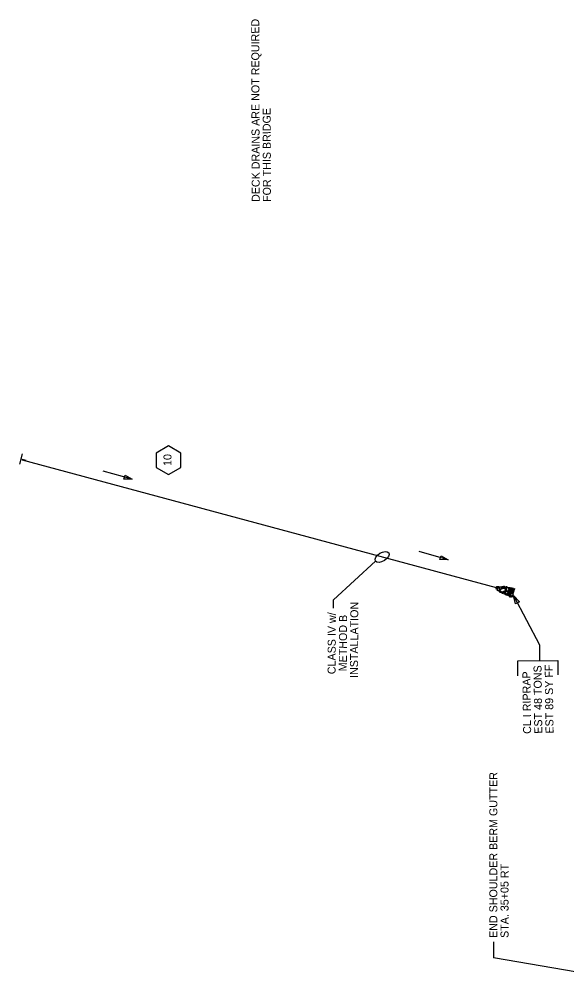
# Model space of a CAD drawing. Extents: x 2384780 to 2405432, y 547869 to 573706.
# Drawn here: x 2395017 to 2395359, y 553697 to 554302 of the extents above; entities that cross this region are included whole.
import ezdxf

# ---------------------------------------------------------------- set-up
doc = ezdxf.new("R2010")
doc.units = 0
for name, color, linetype in [('Old_Level_1', 7, 'Continuous'), ('Old_Level_10', 7, 'Continuous'), ('Old_Level_23', 7, 'Continuous'), ('Old_Level_5', 7, 'Continuous'), ('Prop Drainage Box Number Symbol CELL', 7, 'Continuous')]:
    doc.layers.add(name, color=color, linetype=linetype)

# ---------------------------------------------------------------- blocks, each defined once
blk = doc.blocks.new('RIPRAP')
at = {"layer": 'Old_Level_1'}
for points in [[(-0.002, -0.00625), (-0.00625, -0.00775), (-0.016, -0.0125), (-0.02, -0.00675), (-0.02, -0.003), (-0.008, 0.00275), (-0.002, -0.00025), (-0.002, -0.00625)], [(0.01825, -0.00325), (0.01375, -0.005), (0.00325, -0.00975), (0.00025, -0.00375), (0, 0), (0.01125, 0.005), (0.018, 0.00275), (0.01825, -0.00325)], [(-0.046, -0.12775), (-0.0505, -0.12425), (-0.053, -0.1145), (-0.0485, -0.11), (-0.04475, -0.11), (-0.04, -0.12175), (-0.04225, -0.12625), (-0.046, -0.12775)], [(-0.0485, -0.08525), (-0.0425, -0.0835), (-0.03275, -0.0825), (-0.0305, -0.08925), (-0.03175, -0.0945), (-0.0445, -0.09325), (-0.049, -0.089), (-0.0485, -0.08525)], [(-0.046, -0.1025), (-0.04025, -0.098), (-0.02675, -0.09375), (-0.02, -0.09975), (-0.02, -0.10575), (-0.03625, -0.11225), (-0.044, -0.1085), (-0.046, -0.1025)], [(-0.03675, -0.07275), (-0.04075, -0.06825), (-0.04325, -0.0585), (-0.0395, -0.054), (-0.035, -0.054), (-0.031, -0.0665), (-0.033, -0.0705), (-0.03675, -0.07275)], [(-0.023, -0.1195), (-0.02725, -0.12175), (-0.037, -0.126), (-0.041, -0.1195), (-0.041, -0.11625), (-0.029, -0.1115), (-0.02525, -0.1135), (-0.023, -0.1195)], [(-0.0305, -0.05975), (-0.035, -0.05625), (-0.0375, -0.0465), (-0.033, -0.042), (-0.02925, -0.042), (-0.02475, -0.05375), (-0.02675, -0.05825), (-0.0305, -0.05975)], [(-0.00025, -0.11525), (-0.0145, -0.10575), (-0.0355, -0.078), (-0.0255, -0.056), (-0.00975, -0.051), (0.01725, -0.08475), (0.01525, -0.10425), (0.002, -0.11775)], [(-0.0345, -0.0215), (-0.0265, -0.01775), (-0.007, -0.01125), (0.00375, -0.02075), (0.003, -0.0315), (-0.02075, -0.03775), (-0.03225, -0.032), (-0.0345, -0.024)], [(-0.0275, -0.0395), (-0.023, -0.03925), (-0.014, -0.039), (-0.0115, -0.045), (-0.0115, -0.04875), (-0.0235, -0.049), (-0.0295, -0.04475), (-0.0275, -0.0395)], [(-0.01575, -0.1245), (-0.02025, -0.12125), (-0.022, -0.11125), (-0.0185, -0.10675), (-0.014, -0.10675), (-0.00975, -0.1185), (-0.012, -0.123), (-0.01575, -0.1245)], [(-0.0095, -0.039), (0.00025, -0.0365), (0.0205, -0.036), (0.02775, -0.0495), (0.024, -0.05775), (-0.00075, -0.05675), (-0.009, -0.0485), (-0.0095, -0.039)], [(-0.00575, -0.118), (0.00025, -0.1155), (0.0085, -0.1175), (0.0125, -0.12425), (0.01025, -0.128), (-0.00175, -0.12825), (-0.00575, -0.12175), (-0.00575, -0.118)], [(0.009, -0.07425), (0.0045, -0.07075), (0.00225, -0.061), (0.00625, -0.05625), (0.01, -0.057), (0.01425, -0.06825), (0.01275, -0.072), (0.009, -0.07425)], [(0.012, -0.0355), (0.00825, -0.0295), (0.0035, -0.01775), (0.01025, -0.00925), (0.01825, -0.009), (0.0225, -0.027), (0.01875, -0.033), (0.012, -0.0355)], [(0.01975, -0.07925), (0.01525, -0.07475), (0.01375, -0.06525), (0.01725, -0.0605), (0.02175, -0.0605), (0.02575, -0.07325), (0.0235, -0.077), (0.01975, -0.07925)], [(0.0225, -0.12), (0.0185, -0.11625), (0.01675, -0.10675), (0.0205, -0.102), (0.025, -0.102), (0.0285, -0.114), (0.02625, -0.11775), (0.0225, -0.12)], [(0.02025, -0.07975), (0.02825, -0.07725), (0.04025, -0.077), (0.045, -0.08725), (0.042, -0.0935), (0.02475, -0.092), (0.02025, -0.0855), (0.02025, -0.07975)], [(0.03125, -0.0765), (0.0265, -0.073), (0.02425, -0.06325), (0.0285, -0.0585), (0.03225, -0.05925), (0.03625, -0.0705), (0.035, -0.07425), (0.03125, -0.0765)], [(0.048, -0.1195), (0.04425, -0.12325), (0.036, -0.12575), (0.03, -0.122), (0.02975, -0.1155), (0.04175, -0.11375), (0.04775, -0.11575), (0.048, -0.1195)], [(0.03775, -0.114), (0.03325, -0.11025), (0.031, -0.1005), (0.035, -0.096), (0.03875, -0.09675), (0.043, -0.10775), (0.0415, -0.1115), (0.03775, -0.114)], [(-0.06725, -0.1915), (-0.06125, -0.18975), (-0.0515, -0.18875), (-0.04925, -0.1955), (-0.0505, -0.20075), (-0.06325, -0.1995), (-0.06775, -0.19525), (-0.06725, -0.1915)], [(-0.064, -0.2115), (-0.058, -0.20975), (-0.04825, -0.20875), (-0.046, -0.2155), (-0.04725, -0.22075), (-0.06, -0.2195), (-0.0645, -0.21525), (-0.064, -0.2115)], [(-0.061, -0.17925), (-0.055, -0.17725), (-0.04525, -0.17625), (-0.043, -0.183), (-0.04425, -0.18825), (-0.057, -0.187), (-0.0615, -0.18275), (-0.061, -0.17925)], [(-0.04975, -0.14825), (-0.05425, -0.14475), (-0.05675, -0.135), (-0.05225, -0.1305), (-0.0485, -0.1305), (-0.04375, -0.14225), (-0.046, -0.14675), (-0.04975, -0.14825)], [(-0.04975, -0.17575), (-0.05375, -0.1705), (-0.05675, -0.16075), (-0.05225, -0.157), (-0.04875, -0.157), (-0.04375, -0.169), (-0.046, -0.1735), (-0.04975, -0.17575)], [(-0.032, -0.15425), (-0.03625, -0.15575), (-0.046, -0.158), (-0.0505, -0.15375), (-0.05075, -0.15075), (-0.041, -0.146), (-0.035, -0.14825), (-0.03275, -0.152)], [(-0.05075, -0.19675), (-0.0405, -0.195), (-0.021, -0.194), (-0.01375, -0.208), (-0.018, -0.21775), (-0.042, -0.21675), (-0.0505, -0.20725), (-0.05075, -0.19675)], [(-0.04275, -0.12825), (-0.03225, -0.126), (-0.012, -0.1275), (-0.00575, -0.1395), (-0.009, -0.15), (-0.033, -0.1485), (-0.04375, -0.13875), (-0.04275, -0.12825)], [(-0.0355, -0.17625), (-0.037, -0.1725), (-0.04125, -0.16275), (-0.03525, -0.158), (-0.0315, -0.158), (-0.02675, -0.17075), (-0.031, -0.174), (-0.0355, -0.17625)], [(-0.012, -0.187), (-0.01875, -0.19075), (-0.033, -0.1935), (-0.039, -0.1875), (-0.039, -0.1815), (-0.02275, -0.17675), (-0.01525, -0.17875), (-0.012, -0.187)], [(-0.0215, -0.16975), (-0.02625, -0.1655), (-0.0285, -0.15575), (-0.024, -0.15125), (-0.02025, -0.15175), (-0.01625, -0.163), (-0.01775, -0.1675), (-0.0215, -0.16975)], [(0.00075, -0.15075), (0.0045, -0.15875), (0.011, -0.179), (0.0015, -0.18875), (-0.009, -0.189), (-0.01475, -0.16525), (-0.012, -0.153), (-0.0015, -0.1515)], [(-0.0115, -0.204), (-0.00425, -0.2025), (0.0085, -0.20225), (0.01275, -0.21275), (0.01125, -0.2185), (-0.0075, -0.21675), (-0.01225, -0.21075), (-0.0115, -0.204)], [(0.04, -0.14075), (0.03075, -0.14625), (0.009, -0.15575), (-0.004, -0.14175), (-0.00425, -0.132), (0.024, -0.123), (0.03825, -0.1285), (0.0425, -0.1405)], [(0.00625, -0.2035), (0.00175, -0.19975), (-0.001, -0.19), (0.0035, -0.1855), (0.00725, -0.1855), (0.012, -0.1975), (0.01, -0.202), (0.00625, -0.2035)], [(0.01625, -0.174), (0.0125, -0.17075), (0.009, -0.16), (0.0135, -0.1555), (0.01725, -0.15625), (0.022, -0.168), (0.02075, -0.17175), (0.01625, -0.174)], [(0.026, -0.18075), (0.03225, -0.18875), (0.03875, -0.20825), (0.02925, -0.219), (0.01875, -0.21675), (0.012, -0.193), (0.01575, -0.184), (0.026, -0.17925)], [(0.0205, -0.15575), (0.0265, -0.15325), (0.03475, -0.15525), (0.03875, -0.162), (0.0365, -0.16575), (0.0245, -0.166), (0.0205, -0.1595), (0.0205, -0.15575)], [(0.04925, -0.17425), (0.044, -0.17875), (0.03525, -0.1805), (0.02975, -0.177), (0.0295, -0.171), (0.0415, -0.16925), (0.0475, -0.1705), (0.04925, -0.17425)], [(0.0335, -0.189), (0.0395, -0.18675), (0.04775, -0.18875), (0.0515, -0.1955), (0.04925, -0.19925), (0.03725, -0.1995), (0.0335, -0.19275), (0.0335, -0.189)], [(0.043, -0.162), (0.03825, -0.1585), (0.036, -0.14875), (0.04, -0.144), (0.04375, -0.14475), (0.048, -0.15575), (0.04675, -0.1595), (0.043, -0.162)], [(0.04325, -0.22375), (0.0385, -0.22025), (0.03625, -0.2105), (0.0405, -0.20575), (0.04425, -0.2065), (0.0485, -0.2175), (0.047, -0.22125), (0.04325, -0.22375)]]:
    blk.add_lwpolyline(points, dxfattribs=at)
blk = doc.blocks.new('AH1')
at = {"layer": 'Old_Level_23'}
blk.add_lwpolyline([(-5.28, 1.32), (0, 0), (-5.28, -1.32)], close=True, dxfattribs=at)
blk = doc.blocks.new('HDWL')
at = {"layer": 'Old_Level_1'}
for p, q in [((0, 0), (-0.0685, 0)), ((0, -0.0655), (0, 0.0685))]:
    blk.add_line(p, q, dxfattribs=at)
blk = doc.blocks.new('BUBBLE')
at = {"layer": 'Old_Level_10'}
blk.add_ellipse((0, 0), major_axis=(192, 154), ratio=0.548538, dxfattribs=at)

msp = doc.modelspace()

# ---------------------------------------------------------------- linework, layer by layer
at = {"layer": 'Old_Level_1'}
msp.add_line((2395314.88, 553946.34), (2395018.73, 554026.17), dxfattribs=at)
for points in [[(2395325.52, 553941.63), (2395341.67, 553910.63), (2395341.71, 553900.83)], [(2395328.12, 553891.34), (2395328.08, 553900.77), (2395353.16, 553900.87), (2395353.19, 553892.03)]]:
    msp.add_lwpolyline(points, dxfattribs=at)
at = {"layer": 'Old_Level_5'}
for p, q in [((2395087.29, 554014.16), (2395069.21, 554019.26)), ((2395284.65, 553963.84), (2395266.57, 553968.95)), ((2395239.29, 553963.07), (2395213.06, 553938.75)), ((2395213.06, 553933.72), (2395213.06, 553938.75)), ((2395312.87, 553725.07), (2395312.87, 553715.07)), ((2395417.23, 553697.13), (2395312.87, 553715.07))]:
    msp.add_line(p, q, dxfattribs=at)
for points in [[(2395082.82, 554016.72), (2395087.29, 554014.16), (2395082.14, 554014.32)], [(2395280.18, 553966.41), (2395284.65, 553963.84), (2395279.5, 553964)]]:
    msp.add_lwpolyline(points, close=True, dxfattribs=at)
at = {"layer": 'Prop Drainage Box Number Symbol CELL'}
msp.add_lwpolyline([(2395109.97, 554017.07), (2395117.72, 554021.55), (2395117.72, 554030.49), (2395109.97, 554034.97), (2395102.22, 554030.49), (2395102.22, 554021.55)], close=True, dxfattribs=at)

# ---------------------------------------------------------------- block references
at = {"layer": 'Old_Level_23', "xscale": 0.9999990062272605, "yscale": 0.9999990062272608, "rotation": 117.51248574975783}
msp.add_blockref('AH1', (2395325.52, 553941.63), dxfattribs=at)
at = {"layer": 'Old_Level_5'}
for name, p, xscale, yscale, rotation in [('HDWL', (2395017.68, 554026.93), 50, 49.99999999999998, 164.91429293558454), ('BUBBLE', (2395243.4, 553965.64), 0.019687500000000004, 0.019687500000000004, 173.279012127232), ('RIPRAP', (2395314.88, 553946.34), 50, 49.99999999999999, 74.91429293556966)]:
    msp.add_blockref(name, p, dxfattribs=dict(at, xscale=xscale, yscale=yscale, rotation=rotation))

# ---------------------------------------------------------------- texts
at = {"layer": 'Old_Level_1'}
for s, rotation, p in [('DECK DRAINS ARE NOT REQUIRED', 90.15152, (2395166.94, 554187.46)), ('FOR THIS BRIDGE', 90.15152, (2395173.94, 554187.48)), ('INSTALLATION', 89.69551, (2395228.31, 553890.02)), ('CLASS IV w/', 89.69551, (2395214.32, 553892.36)), ('METHOD B', 89.69551, (2395221.33, 553894.17)), ('CL I RIPRAP', 90.68875, (2395336.48, 553855.13)), ('EST 48 TONS ', 90.68875, (2395343.48, 553855.21)), ('EST 89 SY FF', 90.68875, (2395350.48, 553855.29))]:
    msp.add_text(s, height=5, rotation=rotation, dxfattribs=at).set_placement(p)
at = {"layer": 'Old_Level_5'}
for s, p in [('END SHOULDER BERM GUTTER', (2395315.37, 553727.57)), ('STA. 35+05 RT ', (2395322.37, 553727.57))]:
    msp.add_text(s, height=5, rotation=90, dxfattribs=at).set_placement(p)
at = {"layer": 'Prop Drainage Box Number Symbol CELL'}
msp.add_text('10', height=5, rotation=90, dxfattribs=at).set_placement((2395111.82, 554022.49))

doc.saveas('drawing.dxf')
